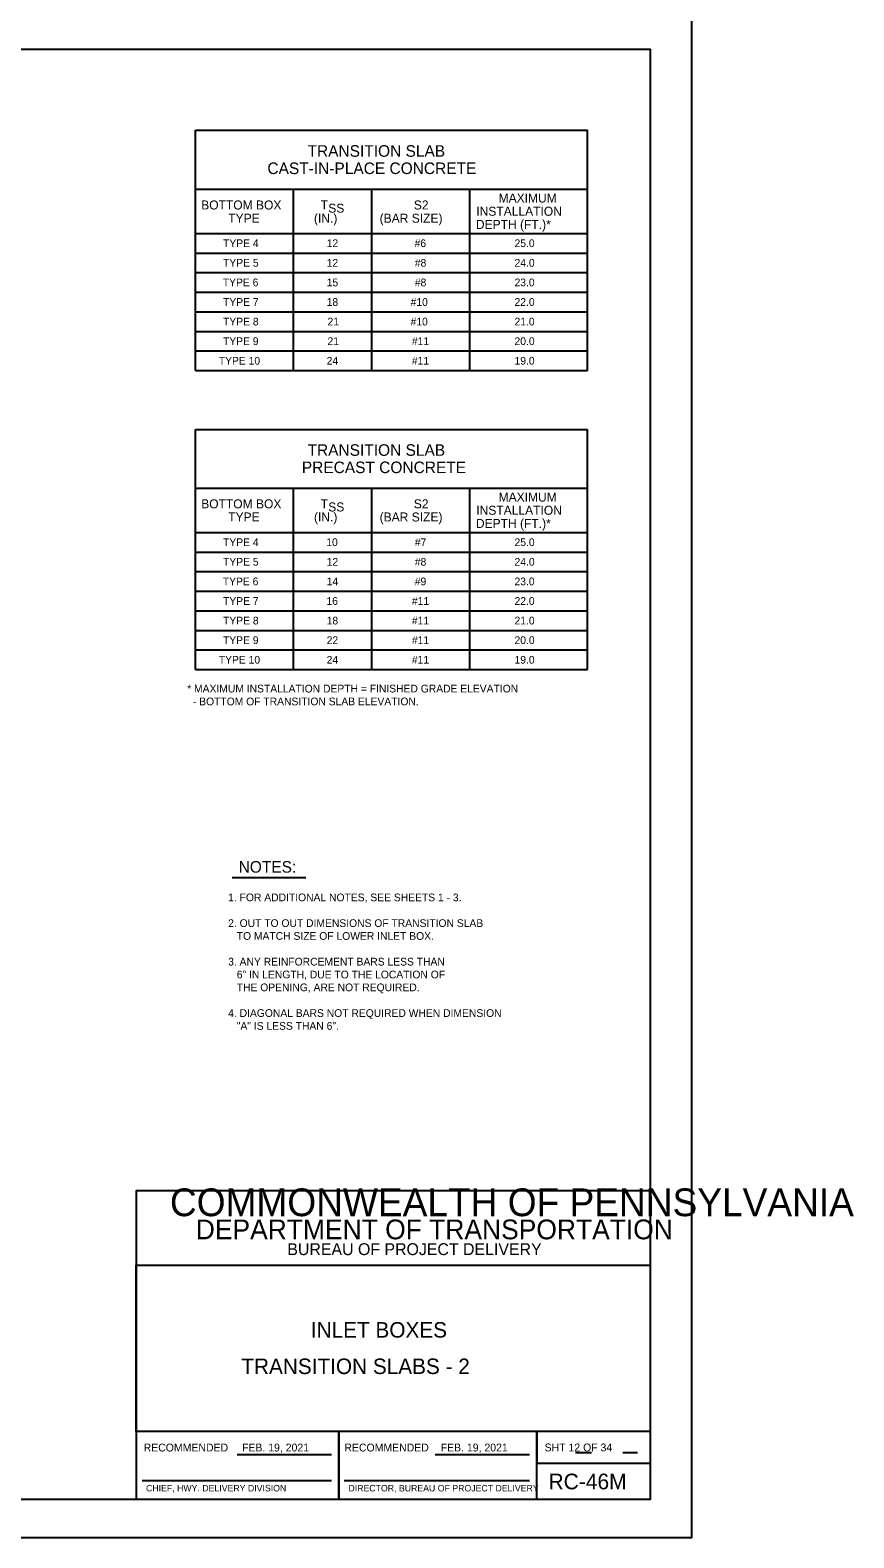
# Model space of a CAD drawing. Extents: x -6420 to 49575, y -4552 to 11624.
# Drawn here: x 9291 to 10342, y 7726 to 9650 of the extents above; entities that cross this region are included whole.
import ezdxf

# ---------------------------------------------------------------- set-up
doc = ezdxf.new("R2010")
doc.units = 0
doc.layers.add('1', color=7, linetype='Continuous')
doc.layers.add('PLT-BNDY', color=7, linetype='Continuous')

msp = doc.modelspace()

# ---------------------------------------------------------------- linework, layer by layer
at = {"layer": '1'}
for p, q in [((9501.9, 9216), (9501.9, 9522.7)), ((9501.9, 9522.7), (10001.9, 9522.7)), ((10001.9, 9216), (10001.9, 9522.7)), ((9501.9, 9447.7), (10001.9, 9447.7)), ((9626.9, 9216), (9626.9, 9447.7)), ((9726.9, 9216), (9726.9, 9447.7)), ((9851.9, 9216), (9851.9, 9447.7)), ((9501.9, 9391), (10001.9, 9391)), ((9501.9, 9366), (10001.9, 9366)), ((9501.9, 9341), (10001.9, 9341)), ((9501.9, 9316), (10001.9, 9316)), ((9501.9, 9291), (10001.9, 9291)), ((9501.9, 9266), (10001.9, 9266)), ((9501.9, 9241), (10001.9, 9241)), ((9501.9, 9216), (10001.9, 9216)), ((9501.9, 8834.4), (9501.9, 9141)), ((9501.9, 9141), (10001.9, 9141)), ((10001.9, 8834.4), (10001.9, 9141)), ((9501.9, 9066), (10001.9, 9066)), ((9626.9, 8834.4), (9626.9, 9066)), ((9726.9, 8834.4), (9726.9, 9066)), ((9851.9, 8834.4), (9851.9, 9066)), ((9501.9, 9009.4), (10001.9, 9009.4)), ((9501.9, 8984.4), (10001.9, 8984.4)), ((9501.9, 8959.4), (10001.9, 8959.4)), ((9501.9, 8934.4), (10001.9, 8934.4)), ((9501.9, 8909.4), (10001.9, 8909.4)), ((9501.9, 8884.4), (10001.9, 8884.4)), ((9501.9, 8859.4), (10001.9, 8859.4)), ((9501.9, 8834.4), (10001.9, 8834.4)), ((9548.8, 8568.9), (9642.6, 8568.9)), ((9555.1, 7832.5), (9675.5, 7832.5)), ((9807.7, 7832.5), (9928.1, 7832.5)), ((9986.8, 7835.1), (10006.9, 7835.1)), ((10047.2, 7835.1), (10066, 7835.1)), ((9433.9, 7799.4), (9675.5, 7799.4)), ((9691.6, 7799.4), (9928.1, 7799.4))]:
    msp.add_line(p, q, dxfattribs=at)
msp.add_lwpolyline([(10082.3, 7775.5), (10082.3, 9625.9), (7503.5, 9625.9), (7503.5, 7775.5), (10082.3, 7775.5), (10082.3, 7862), (9426.1, 7862), (9426.1, 8074.1), (10082.3, 8074.1), (10082.3, 8169.2), (9426.1, 8169.2), (9426.1, 7775.5), (9684.6, 7775.5), (9684.6, 7862), (9684.6, 7775.5), (9937.3, 7775.5), (9937.3, 7862), (9937.3, 7821.5), (10082.3, 7821.5)], dxfattribs=at)
at = {"layer": 'PLT-BNDY'}
msp.add_lwpolyline([(7375.6, 9675.1), (10134.8, 9675.1), (10134.8, 7726.3), (7375.6, 7726.3)], close=True, dxfattribs=at)

# ---------------------------------------------------------------- texts
at = {"layer": '1'}
for s, height, p in [('TRANSITION SLAB', 14.764, (9644.8, 9488.9)), ('CAST-IN-PLACE CONCRETE', 14.764, (9593.6, 9466.8)), ('BOTTOM BOX', 11.48, (9509.1, 9421.6)), ('T  ', 11.48, (9661.6, 9421.6)), ('SS', 11.48, (9671.2, 9417.5)), ('S2', 11.48, (9780.4, 9421.6)), ('MAXIMUM', 11.48, (9888.6, 9430.5)), ('TYPE', 11.48, (9543.6, 9404.7)), ('(IN.)', 11.48, (9653, 9404.7)), ('(BAR SIZE)', 11.48, (9736.8, 9404.7)), ('INSTALLATION', 11.483, (9860.1, 9413.6)), ('DEPTH (FT.)*', 11.483, (9859.6, 9396.8)), ('TYPE 4', 9.84, (9537, 9373.6)), ('12', 9.84, (9669.2, 9373.6)), ('#6', 9.84, (9781.4, 9373.6)), ('25.0', 9.84, (9908.9, 9373.6)), ('TYPE 5', 9.84, (9537, 9348.6)), ('12', 9.84, (9669.2, 9348.6)), ('#8', 9.84, (9781.7, 9348.6)), ('24.0', 9.84, (9908.9, 9348.6)), ('TYPE 6', 9.84, (9536.7, 9323.6)), ('15', 9.84, (9669.2, 9323.6)), ('#8', 9.84, (9781.7, 9323.6)), ('23.0', 9.84, (9908.9, 9323.6)), ('TYPE 7', 9.84, (9537, 9298.6)), ('18', 9.84, (9669.2, 9298.6)), ('#10', 9.84, (9776.3, 9298.6)), ('22.0', 9.84, (9908.9, 9298.6)), ('TYPE 8', 9.84, (9537, 9273.6)), ('21', 9.84, (9670.3, 9273.6)), ('#10', 9.84, (9776.3, 9273.6)), ('21.0', 9.84, (9908.9, 9273.6)), ('TYPE 9', 9.84, (9536.9, 9248.6)), ('21', 9.84, (9670.3, 9248.6)), ('#11', 9.84, (9777.9, 9248.6)), ('20.0', 9.84, (9908.9, 9248.6)), ('TYPE 10', 9.84, (9531.6, 9223.6)), ('24', 9.84, (9669.2, 9223.6)), ('#11', 9.84, (9777.9, 9223.6)), ('19.0', 9.84, (9908.9, 9223.6)), ('TRANSITION SLAB', 14.764, (9644.8, 9107.2)), ('PRECAST CONCRETE', 14.764, (9637.5, 9085.1)), ('BOTTOM BOX', 11.48, (9509.1, 9040.2)), ('T  ', 11.48, (9661.6, 9040.2)), ('SS', 11.48, (9671.2, 9036.2)), ('S2', 11.48, (9780.4, 9040.2)), ('MAXIMUM', 11.48, (9888.6, 9048.8)), ('TYPE', 11.48, (9543.6, 9023.4)), ('(IN.)', 11.48, (9653, 9023.4)), ('(BAR SIZE)', 11.48, (9736.8, 9023.4)), ('DEPTH (FT.)*', 11.483, (9859.6, 9015.2)), ('INSTALLATION', 11.483, (9860.1, 9032)), ('TYPE 4', 9.84, (9537, 8992)), ('10', 9.84, (9668.7, 8992)), ('#7', 9.84, (9781.7, 8992)), ('25.0', 9.84, (9908.9, 8992)), ('TYPE 5', 9.84, (9537, 8967)), ('12', 9.84, (9669.2, 8967)), ('#8', 9.84, (9781.7, 8967)), ('24.0', 9.84, (9908.9, 8967)), ('TYPE 6', 9.84, (9536.7, 8942)), ('14', 9.84, (9669.2, 8942)), ('#9', 9.84, (9781.6, 8942)), ('23.0', 9.84, (9908.9, 8942)), ('TYPE 7', 9.84, (9537, 8917)), ('16', 9.84, (9668.9, 8917)), ('#11', 9.84, (9777.9, 8917)), ('22.0', 9.84, (9908.9, 8917)), ('TYPE 8', 9.84, (9537, 8892)), ('18', 9.84, (9669.2, 8892)), ('#11', 9.84, (9777.9, 8892)), ('21.0', 9.84, (9908.9, 8892)), ('TYPE 9', 9.84, (9536.9, 8867)), ('22', 9.84, (9669.2, 8867)), ('#11', 9.84, (9777.9, 8867)), ('20.0', 9.84, (9908.9, 8867)), ('TYPE 10', 9.84, (9531.6, 8842)), ('24', 9.84, (9669.2, 8842)), ('#11', 9.84, (9777.9, 8842)), ('19.0', 9.84, (9908.9, 8842)), ('* MAXIMUM INSTALLATION DEPTH = FINISHED GRADE ELEVATION', 9.843, (9491.2, 8805.2)), ('  - BOTTOM OF TRANSITION SLAB ELEVATION.', 9.843, (9491.2, 8788.8)), ('NOTES:', 14.76, (9556.9, 8575.2)), ('1. FOR ADDITIONAL NOTES, SEE SHEETS 1 - 3.', 9.843, (9543.5, 8538.7)), ('2. OUT TO OUT DIMENSIONS OF TRANSITION SLAB ', 9.843, (9543.5, 8505.9)), ('   TO MATCH SIZE OF LOWER INLET BOX.', 9.843, (9543.5, 8489.5)), ('3. ANY REINFORCEMENT BARS LESS THAN ', 9.843, (9543.5, 8456.7)), ('   6" IN LENGTH, DUE TO THE LOCATION OF', 9.843, (9543.5, 8440.3)), ('   THE OPENING, ARE NOT REQUIRED.', 9.843, (9543.5, 8423.9)), ('4. DIAGONAL BARS NOT REQUIRED WHEN DIMENSION', 9.843, (9543.5, 8391.1)), ('   "A" IS LESS THAN 6".', 9.843, (9543.5, 8374.7)), ('COMMONWEALTH OF PENNSYLVANIA', 35.379, (9469.2, 8136.8)), ('DEPARTMENT OF TRANSPORTATION', 25.211, (9502.2, 8107.3)), ('BUREAU OF PROJECT DELIVERY', 15.164, (9619, 8087.1)), ('INLET BOXES', 19.816, (9649, 7981.8)), ('TRANSITION SLABS - 2', 19.816, (9560.3, 7935.3)), ('RECOMMENDED', 10, (9435.7, 7836.5)), ('FEB. 19, 2021', 10, (9561.2, 7836.5)), ('RECOMMENDED', 10, (9691.8, 7836.5)), ('FEB. 19, 2021', 10, (9814.7, 7836.5)), ('SHT 12 OF 34', 10, (9947.3, 7836.6)), ('CHIEF, HWY. DELIVERY DIVISION', 8.333, (9438.7, 7785.5)), ('DIRECTOR, BUREAU OF PROJECT DELIVERY', 8.333, (9697, 7785.5)), ('RC-46M', 20, (9952.3, 7788.2))]:
    msp.add_text(s, height=height, dxfattribs=at).set_placement(p)

doc.saveas('drawing.dxf')
